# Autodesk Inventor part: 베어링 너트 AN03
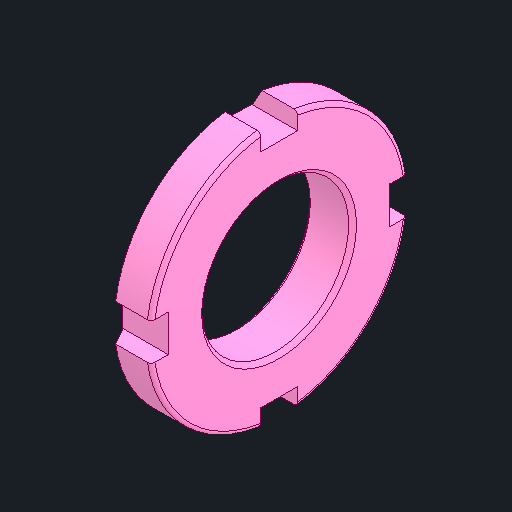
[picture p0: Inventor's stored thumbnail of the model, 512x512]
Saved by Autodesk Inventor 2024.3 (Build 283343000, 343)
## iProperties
Created: 2025-03
Part Number: 베어링 너트 AN03
Material: 강철, 연강
Description: 홈붙이 둥근 너트
Document SubType Name: Modeling
Designer: user
Density: 7.85 g/cm^3
Appearance: 기본값
Author: jhkim
Sending System: Autodesk Inventor 2025
Preprocessor: ST-DEVELOPER v20
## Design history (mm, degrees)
feature "Solid1"
node "솔리드1"
